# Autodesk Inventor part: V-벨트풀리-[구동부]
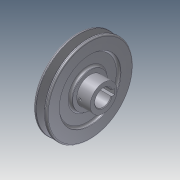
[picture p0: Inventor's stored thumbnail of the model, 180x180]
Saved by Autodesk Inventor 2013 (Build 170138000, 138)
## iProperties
Company: 한국ATC센터
Created: 2014-10
Part Number: V-벨트풀리-[구동부]
Document SubType Name: Modeling
Designer: 한국ATC센터
Density: 7.86 g/cm^3
Material: 강철, 연강
Mass: 1515.01 g
Surface Area: 468.125 cm^2
Volume: 192.75 cm^3
Author: KYOUNG IL JANG
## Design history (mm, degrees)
sketch "스케치1"
  geometry: L1 (-20, 0)-(20, 0); L2 (-20, 0)-(-20, 26); L3 (-20, 26)-(-16, 26); L4 (-16, 26)-(-16, 46); L5 (-16, 46)-(-20, 46); L6 (-20, 46)-(-20, 64.5); L7 (-20, 64.5)-(-16.062, 64.5); L8 (-16.062, 64.5)-(-12.001, 52); L9 (-12.001, 52)-(-7.999, 52); L10 (-7.999, 52)-(-3.938, 64.5); L11 (-3.938, 64.5)-(0, 64.5); L12 (0, 64.5)-(0, 46); L13 (0, 46)-(-4, 46); L14 (-4, 46)-(-4, 26); L15 (-4, 26)-(0, 26); L16 (0, 26)-(0, 20); L17 (0, 20)-(20, 20); L18 (20, 20)-(20, 0); L19 (-14.6, 60)-(-5.4, 60); 2 further points
  constraints: 38 end point, 11 parallel, 7 collinear, 3 equal length, 3 perpendicular, 2 point on line, 1 coincident, 1 horizontal, 1 midpoint
  dimensions: "d0" = 40 distance of L1.start L1.end; "d1" = 4.5 distance between parallel lines of L7 L19; "d2" = 8 distance between parallel lines of L9 L19; "d3" = 9.2 distance of L19.start L19.end; "d4" = 36 deg angle of L10 L8; "d5" = 20 distance between parallel lines of L12 L6; "d6" = 120 diameter of L19 L1; "d7" = 4 distance of L2.end L3.end; "d8" = 52 diameter of L3 L1; "d9" = 92 diameter of L5 L1; "d10" = 40 diameter of L17 L1
revolve "회전1" sketch "스케치1" stored, may be unused: angle "d11" = 90 deg
sketch "스케치2"
  geometry: L1 (-4, 11.843)-(-4, 16.5); L2 (-4, 16.5)-(4, 16.5); L3 (4, 16.5)-(4, 11.843); A1 r 12.5 centre (0, 0) between (-4, 11.843) and (4, 11.843); 1 further point
  constraints: 6 end point, 2 parallel, 2 point on circle, 1 centre point, 1 coincident, 1 horizontal, 1 vertical
  dimensions: "d12" = 25 diameter of A1; "d13" = 8 distance of L1.end L2.end; "d14" = 29 dimension on A1 L2
extrude "돌출1" cut sketch "스케치2" stored distance "d15" = 10; taper "d16" = 0 deg
chamfer "모따기1" distance "d17" = 1; stored, may be unused: second distance "d18" = 2, angle "d19" = 45 deg
node "작업 평면1"
sketch "스케치3"
  geometry: L1 (10, -20)-(10, 20) reference; 3 further points
  constraints: 1 horizontal alignment, 1 midpoint
  dimensions: "d20" = 15 distance from line of L1 point (-5, 0)
hole "구멍1" sketch "스케치3" at (-5, 0) diameter "d21" = 4.459; stored, may be unused: countersink angle "d25" = 90 deg, drill point angle "d27" = 118 deg; dims "d22" = 6, "d23" = 4, "d24" = 2, "d26" = 8
fillet "모깎기1" dims "d28" = 3, "d29" = 2, "d30" = 0.5, "d31" = 1
node "솔리드1"
